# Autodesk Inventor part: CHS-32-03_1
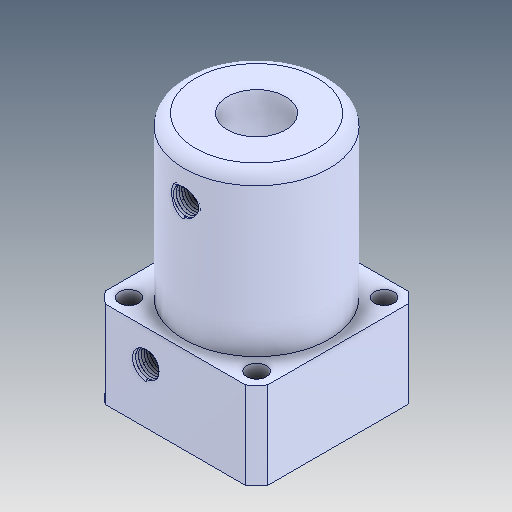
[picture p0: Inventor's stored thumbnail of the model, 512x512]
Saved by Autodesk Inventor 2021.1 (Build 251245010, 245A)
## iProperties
Created: 2021-05
Part Number: CHS-32-03_1
Material: Ogólny
Document SubType Name: Modeling
Designer: user
Density: 1 g/cm^3
Appearance: Domyślna
Author: user
Revision Number: ÈÎºÎ
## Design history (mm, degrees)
feature "Í¹Ì¨-À­Éì1"
node "Bryła1"
